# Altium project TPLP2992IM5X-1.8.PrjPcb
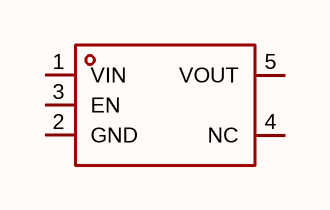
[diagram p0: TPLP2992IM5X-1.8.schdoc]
1 sheet, 1 parts. Net scope: global (net labels, ports and power ports of the same name join across sheets).

## Sheet TPLP2992IM5X-1.8.schdoc
size 127 x 101 mm

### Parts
U?  tplp2992im5x-1.8  [SOT-23-5_L3.0-W1.5-P0.95-LS2.8-BL]  (value not drawn)

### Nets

Not connected (* = marked no-connect by the designer): U? 1(VIN) 2(GND) 3(EN) 4(NC) 5(VOUT)

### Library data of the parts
U? = tplp2992im5x-1.8: 输出极性:正极;工作电压:24V;输出电压:1.8V;输出电流:300mA;电源纹波抑制比(PSRR):70dB@(1kHz);输出类型:固定;; Manufacturer: TECH PUBLIC(台舟); AddInBom: yes; ModelId: 424d41c645fb4cc2a3598f66fad27964; ModelTransform: 118.11,110.236,0,0,0,0,0,0,0; Output Configuration: 正极; Voltage - Supply: 24V; Output Voltage: 1.8V; Output Current: 300mA; Voltage Dropout: 500mV@(100mA); standby current: 2uA; Output Type: 固定; Number of Outputs: 1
